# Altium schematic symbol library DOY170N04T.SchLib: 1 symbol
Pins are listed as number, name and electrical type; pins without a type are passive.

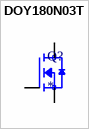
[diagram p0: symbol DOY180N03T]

## DOY180N03T
designator Q?
1.2mOHM RDS(on), 30V, 128A(tc) & 180A(ta), 40nC
footprint DOY180N03T
pins: 1 S1, 2 S2, 3 S3, 4 G, 5 D1, 6 D2, 7 D3, 8 D4, 9 D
